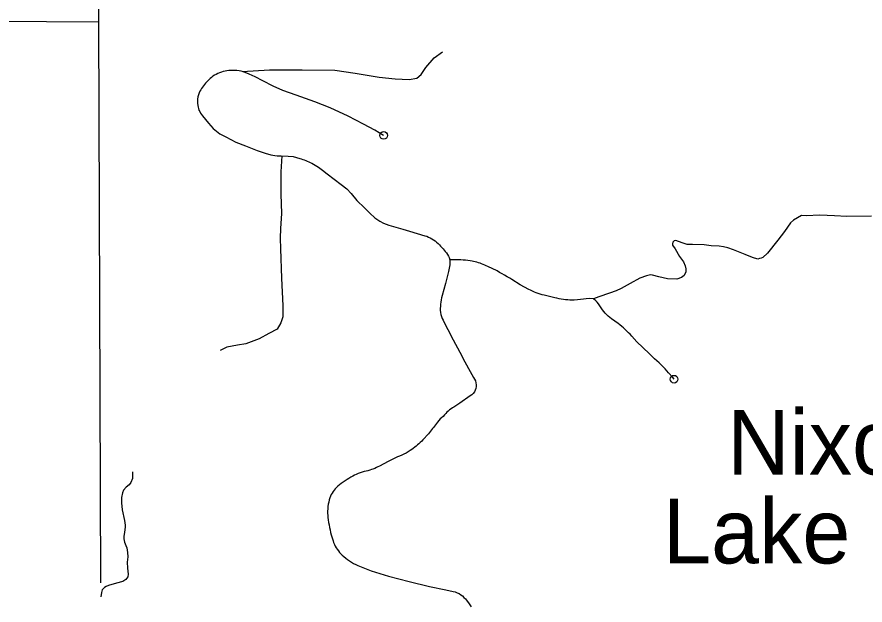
# Model space of a CAD drawing. Extents: x -19 to 366, y -4 to 359.
# Drawn here: x 139.293 to 140.343, y 191.293 to 192.02 of the extents above; entities that cross this region are included whole.
import ezdxf

# ---------------------------------------------------------------- set-up
doc = ezdxf.new("R2010")
doc.units = 0
for name, color, linetype in [('Level 2', 7, 'Continuous'), ('Level 31', 7, 'Continuous'), ('Level 32', 7, 'Continuous'), ('Level 35', 7, 'Continuous'), ('Level 60', 7, 'Continuous'), ('Level 63', 7, 'Continuous')]:
    doc.layers.add(name, color=color, linetype=linetype)

msp = doc.modelspace()

# ---------------------------------------------------------------- linework, layer by layer
at = {"layer": 'Level 2'}
for points in [[(138.4888, 192.0199), (139.3943, 192.0138)], [(139.3964, 191.3199), (139.3943, 192.0138)]]:
    msp.add_lwpolyline(points, dxfattribs=at)
at = {"layer": 'Level 31'}
for points in [[(139.7467, 191.8735), (139.7356, 191.8801), (139.7219, 191.8875), (139.7027, 191.8973), (139.6806, 191.9075), (139.6614, 191.915), (139.6385, 191.9231), (139.622, 191.929), (139.6098, 191.9344), (139.5972, 191.9411), (139.5878, 191.946), (139.5803, 191.9493), (139.573, 191.9522), (139.5704, 191.9528), (139.5678, 191.9533), (139.5651, 191.9536), (139.5625, 191.9538), (139.5599, 191.9538), (139.5572, 191.9538), (139.5551, 191.9536), (139.5527, 191.9533), (139.5504, 191.953), (139.5481, 191.9524), (139.5459, 191.9518), (139.5437, 191.951), (139.5415, 191.9501), (139.5394, 191.949), (139.5373, 191.9479), (139.5354, 191.9466), (139.5335, 191.9452), (139.5319, 191.9439), (139.5305, 191.9425), (139.529, 191.941), (139.5276, 191.9395), (139.5263, 191.938), (139.525, 191.9364), (139.5237, 191.9348), (139.5225, 191.9332), (139.5213, 191.9315), (139.5202, 191.9298), (139.5191, 191.9281), (139.5182, 191.9262), (139.5173, 191.9237), (139.5166, 191.9211), (139.5162, 191.9185), (139.5161, 191.9159), (139.5161, 191.9132), (139.5165, 191.9106), (139.5169, 191.9086), (139.5174, 191.9067), (139.5181, 191.9048), (139.519, 191.903), (139.52, 191.9012), (139.5211, 191.8994), (139.5224, 191.8978), (139.5298, 191.8885), (139.5357, 191.882), (139.5377, 191.8802), (139.5398, 191.8786), (139.5419, 191.877), (139.5441, 191.8755), (139.5464, 191.8742), (139.5488, 191.873), (139.5512, 191.8719), (139.5639, 191.8653), (139.5756, 191.8605), (139.5902, 191.8549), (139.6, 191.8516), (139.607, 191.8496), (139.6096, 191.849), (139.6121, 191.8486), (139.6147, 191.8483), (139.6173, 191.8482), (139.6199, 191.8482), (139.6284, 191.848), (139.6345, 191.8474), (139.6428, 191.8451), (139.6447, 191.8446), (139.6466, 191.8439), (139.6485, 191.8433), (139.6504, 191.8425), (139.6522, 191.8417), (139.654, 191.8409), (139.6558, 191.84), (139.6576, 191.8391), (139.666, 191.8342), (139.6709, 191.8304), (139.6769, 191.826), (139.6855, 191.8193), (139.694, 191.8128), (139.701, 191.8074), (139.7066, 191.8016), (139.7137, 191.793), (139.723, 191.7838), (139.7295, 191.7775), (139.7358, 191.7717), (139.7421, 191.7673), (139.7465, 191.7651), (139.7533, 191.7624), (139.7617, 191.7599)], [(139.6207, 191.8481), (139.6195, 191.8283), (139.6195, 191.8008), (139.6201, 191.777), (139.619, 191.7585), (139.6184, 191.7465), (139.619, 191.7334), (139.6201, 191.697), (139.6219, 191.6629), (139.6219, 191.6492), (139.6195, 191.6415), (139.6148, 191.6337), (139.6046, 191.6283), (139.5927, 191.6218), (139.576, 191.6158), (139.5659, 191.614), (139.5527, 191.6116), (139.5444, 191.6074)], [(139.7617, 191.7599), (139.7706, 191.7576), (139.7788, 191.7549), (139.7882, 191.7523), (139.7978, 191.7495), (139.8, 191.7487), (139.8022, 191.7478), (139.8044, 191.7468), (139.8065, 191.7456), (139.8085, 191.7444), (139.8104, 191.743), (139.8123, 191.7415), (139.8141, 191.7399), (139.8157, 191.7383), (139.8172, 191.7366), (139.8187, 191.735), (139.8202, 191.7333), (139.8216, 191.7316), (139.823, 191.7299), (139.8243, 191.7281), (139.8256, 191.7263), (139.8268, 191.7243), (139.8277, 191.7224), (139.8285, 191.7196)], [(139.8285, 191.7196), (139.8288, 191.7174), (139.8288, 191.7153), (139.8286, 191.7133), (139.8282, 191.7113), (139.8271, 191.705), (139.8233, 191.6905), (139.8191, 191.6755), (139.8184, 191.6728), (139.8178, 191.6701), (139.8174, 191.6674), (139.8171, 191.6646), (139.8169, 191.6619), (139.8168, 191.6598), (139.8168, 191.6572), (139.817, 191.6546), (139.8175, 191.6521), (139.8182, 191.6496), (139.8191, 191.6472), (139.8202, 191.6449), (139.8213, 191.643), (139.8263, 191.6335), (139.8327, 191.6208), (139.8409, 191.6054), (139.8472, 191.5935), (139.8537, 191.5815), (139.858, 191.574), (139.8593, 191.572), (139.8603, 191.5699), (139.861, 191.5676), (139.8613, 191.5652), (139.8613, 191.5629), (139.8608, 191.5605), (139.8601, 191.5583), (139.859, 191.5562), (139.8576, 191.5543), (139.8558, 191.5527), (139.8539, 191.5513), (139.841, 191.5422), (139.8337, 191.5375), (139.8318, 191.5365), (139.8301, 191.5353), (139.8283, 191.534), (139.8267, 191.5326), (139.8251, 191.5311), (139.8236, 191.5295), (139.822, 191.5278), (139.8202, 191.526), (139.8184, 191.5243), (139.8166, 191.5228), (139.8133, 191.5187), (139.8121, 191.5171), (139.8109, 191.5155), (139.8097, 191.5139), (139.8085, 191.5123), (139.8072, 191.5108), (139.806, 191.5092), (139.8047, 191.5077), (139.8035, 191.5061), (139.8022, 191.5046), (139.7954, 191.497), (139.7938, 191.4954), (139.7921, 191.4938), (139.7904, 191.4922), (139.7887, 191.4907), (139.787, 191.4892), (139.7852, 191.4878), (139.7834, 191.4864), (139.7816, 191.4851), (139.7795, 191.4836), (139.7769, 191.482), (139.7744, 191.4806), (139.7717, 191.4792), (139.7691, 191.478), (139.7664, 191.4769), (139.7637, 191.4759), (139.7524, 191.4701), (139.7417, 191.4644), (139.7397, 191.4635), (139.7377, 191.4626), (139.7356, 191.4617), (139.7335, 191.4609), (139.7315, 191.4601), (139.7294, 191.4594), (139.7272, 191.4588), (139.7251, 191.4582), (139.7226, 191.4577), (139.7201, 191.457), (139.7176, 191.4562), (139.7152, 191.4553), (139.7128, 191.4543), (139.7105, 191.4531), (139.7087, 191.4522), (139.7062, 191.4508), (139.7038, 191.4493), (139.7014, 191.4478), (139.699, 191.4462), (139.6966, 191.4446), (139.6943, 191.443), (139.692, 191.4413)], [(140.0066, 191.6715), (140.0012, 191.6717), (139.9975, 191.6713), (139.9939, 191.6708), (139.9902, 191.6704), (139.9865, 191.67), (139.9827, 191.6696), (139.98, 191.6697), (139.9773, 191.6699), (139.9746, 191.6701), (139.9719, 191.6703), (139.9692, 191.6707), (139.9665, 191.671), (139.9638, 191.6715), (139.9611, 191.672), (139.9585, 191.6726), (139.9454, 191.6759), (139.9429, 191.6765), (139.9405, 191.6773), (139.9381, 191.6781), (139.9357, 191.6789), (139.9334, 191.6798), (139.931, 191.6808), (139.9283, 191.682), (139.9264, 191.6828), (139.9157, 191.6887), (139.9054, 191.6951), (139.9027, 191.6968), (139.8996, 191.6987), (139.8965, 191.7005), (139.8934, 191.7023), (139.8902, 191.7041), (139.8871, 191.7059), (139.8756, 191.7114), (139.8738, 191.7123), (139.8719, 191.7131), (139.87, 191.7139), (139.868, 191.7147), (139.8661, 191.7154), (139.8641, 191.7161), (139.8621, 191.7167), (139.8601, 191.7172), (139.8581, 191.7177), (139.8561, 191.7181), (139.8539, 191.7185), (139.851, 191.7189), (139.8481, 191.7192), (139.8452, 191.7194), (139.8423, 191.7195), (139.8393, 191.7195), (139.8355, 191.7196), (139.8321, 191.7196), (139.8285, 191.7196)], [(140.1063, 191.572), (140.1048, 191.5742), (140.0995, 191.5798), (140.095, 191.5849), (140.0878, 191.5924), (140.0821, 191.5973), (140.0758, 191.6033), (140.0676, 191.6112), (140.0603, 191.6183), (140.0538, 191.6254), (140.0518, 191.6275), (140.0498, 191.6295), (140.0478, 191.6315), (140.0457, 191.6335), (140.0436, 191.6354), (140.0414, 191.6373), (140.0392, 191.6391), (140.037, 191.6409), (140.0289, 191.6467), (140.0268, 191.6483), (140.0247, 191.6499), (140.0228, 191.6517), (140.0209, 191.6536), (140.0192, 191.6555), (140.0175, 191.6576), (140.0126, 191.6653), (140.011, 191.6671), (140.0092, 191.6687), (140.0066, 191.6715)], [(139.692, 191.4413), (139.6898, 191.4395), (139.6882, 191.4381), (139.6867, 191.4365), (139.6854, 191.4348), (139.6841, 191.433), (139.6829, 191.4311), (139.6819, 191.4292), (139.681, 191.4272), (139.6802, 191.4252), (139.6794, 191.4226), (139.6787, 191.4199), (139.6782, 191.4172), (139.6777, 191.4145), (139.6774, 191.4117), (139.6773, 191.4089), (139.6773, 191.4061), (139.6774, 191.4033), (139.6777, 191.401), (139.6781, 191.3979), (139.6786, 191.3948), (139.6791, 191.3917), (139.6797, 191.3886), (139.6804, 191.3855), (139.6811, 191.3825), (139.6819, 191.3794), (139.6833, 191.3744), (139.684, 191.3721), (139.6848, 191.3699), (139.6857, 191.3677), (139.6868, 191.3656), (139.6879, 191.3635), (139.6892, 191.3616), (139.6906, 191.3596), (139.6921, 191.3578), (139.6938, 191.3561), (139.6955, 191.3544), (139.6975, 191.3527), (139.6997, 191.3508), (139.702, 191.349), (139.7044, 191.3473), (139.7069, 191.3457), (139.7095, 191.3442), (139.7121, 191.3429), (139.7147, 191.3416), (139.7313, 191.3349), (139.7528, 191.3285), (139.7783, 191.3217), (139.8035, 191.3155), (139.8238, 191.3115), (139.8328, 191.3095), (139.8353, 191.3088), (139.8377, 191.3079), (139.84, 191.3068), (139.8422, 191.3054), (139.8442, 191.3039), (139.8461, 191.3021), (139.8479, 191.3002), (139.8492, 191.2985), (139.8525, 191.294), (139.8551, 191.2905)]]:
    msp.add_lwpolyline(points, dxfattribs=at)
for centre in [(139.7467, 191.8735), (140.1063, 191.572)]:
    msp.add_circle(centre, 0.00473, dxfattribs=at)
at = {"layer": 'Level 32'}
for points in [[(139.5716, 191.9525), (139.6052, 191.9547), (139.6458, 191.9547), (139.6864, 191.9541), (139.7114, 191.9505), (139.7413, 191.9457), (139.7609, 191.9433), (139.7782, 191.9427), (139.7878, 191.9445), (139.7932, 191.9487), (139.7991, 191.9576), (139.8093, 191.9696), (139.8194, 191.9767)], [(140.3507, 191.7736), (140.32, 191.7732), (140.3047, 191.7742), (140.2867, 191.7747), (140.2698, 191.7742), (140.2639, 191.7745), (140.2588, 191.7716), (140.2542, 191.7688), (140.2503, 191.7655), (140.243, 191.7546), (140.2345, 191.7438), (140.2219, 191.7279), (140.2159, 191.7225), (140.2139, 191.7217), (140.2119, 191.7211), (140.2098, 191.7206), (140.2034, 191.7224), (140.1944, 191.7261), (140.1796, 191.732), (140.1729, 191.7345), (140.1672, 191.7358), (140.162, 191.7364), (140.1523, 191.7371), (140.1435, 191.7381), (140.1289, 191.7384), (140.1225, 191.7387), (140.1163, 191.7407), (140.1082, 191.7435), (140.1062, 191.743), (140.1048, 191.7416), (140.1041, 191.7396), (140.1043, 191.7376), (140.1074, 191.7333), (140.1131, 191.7238), (140.1177, 191.7171), (140.1199, 191.7122), (140.1209, 191.7085), (140.1206, 191.7049), (140.1187, 191.7002), (140.1156, 191.6976), (140.1098, 191.6959), (140.0979, 191.6961), (140.0875, 191.6985), (140.0796, 191.7007), (140.0771, 191.7011), (140.0722, 191.7), (140.0639, 191.6968), (140.0518, 191.6905), (140.0409, 191.6843), (140.0344, 191.6814), (140.0261, 191.6784), (140.0129, 191.6738), (140.0066, 191.6715)], [(139.4357, 191.4576), (139.4358, 191.4528), (139.4357, 191.4492), (139.4337, 191.4444), (139.4317, 191.4413), (139.4279, 191.4384), (139.4246, 191.4348), (139.4234, 191.4315), (139.4221, 191.4257), (139.4221, 191.419), (139.4232, 191.4106), (139.4259, 191.397), (139.4267, 191.3916), (139.4268, 191.389), (139.4257, 191.3826), (139.425, 191.3774), (139.4251, 191.3746), (139.4261, 191.3705), (139.4275, 191.3663), (139.4289, 191.3633), (139.4297, 191.3575), (139.4301, 191.3521), (139.4294, 191.3458), (139.4296, 191.3381), (139.4303, 191.3308), (139.4299, 191.3276), (139.4277, 191.3243), (139.4237, 191.3216), (139.4158, 191.3196), (139.4062, 191.317), (139.403, 191.3156), (139.4011, 191.3142), (139.3984, 191.3116), (139.3975, 191.3083), (139.3964, 191.3028)]]:
    msp.add_lwpolyline(points, dxfattribs=at)
at = {"layer": 'Level 60'}
for points in [[(146.7783, 1.697), (146.5788, 10.3131), (146.3785, 18.9294), (146.1776, 27.5458), (145.9759, 36.1624), (145.7736, 44.7791), (145.5705, 53.396), (145.3668, 62.013), (145.1624, 70.6301), (144.9572, 79.2474), (144.7514, 87.8648), (144.5449, 96.4823), (144.3377, 105.1), (144.1299, 113.7179), (143.9213, 122.3359), (143.712, 130.954), (143.5021, 139.5723), (143.2915, 148.1907), (143.0802, 156.8092), (142.8682, 165.4279), (142.6555, 174.0468), (142.4422, 182.6658), (142.2282, 191.2849), (142.0135, 199.9042), (141.7981, 208.5236), (141.582, 217.1432), (141.3653, 225.7629), (141.1479, 234.3828), (140.9298, 243.0028), (140.711, 251.623), (140.4916, 260.2433), (140.2715, 268.8638), (140.0508, 277.4844), (139.8293, 286.1051), (139.6072, 294.726), (139.3845, 303.3471), (139.161, 311.9683), (138.937, 320.5896), (138.7122, 329.2111), (138.4868, 337.8328), (138.2607, 346.4546)], [(139.4406, 1.5315), (139.2511, 10.1473), (139.0608, 18.7633), (138.8699, 27.3793), (138.6784, 35.9956), (138.4861, 44.6119), (138.2932, 53.2285), (138.0997, 61.8451), (137.9055, 70.4619), (137.7106, 79.0789), (137.5151, 87.6959), (137.319, 96.3132), (137.1221, 104.9306), (136.9247, 113.5481), (136.7265, 122.1658), (136.5278, 130.7836), (136.3283, 139.4016), (136.1282, 148.0197), (135.9275, 156.6379), (135.7261, 165.2564), (135.5241, 173.8749), (135.3214, 182.4936), (135.1181, 191.1125), (134.9141, 199.7315), (134.7095, 208.3506), (134.5043, 216.9699), (134.2984, 225.5894), (134.0919, 234.209), (133.8847, 242.8288), (133.6769, 251.4487), (133.4685, 260.0687), (133.2594, 268.6889), (133.0497, 277.3093), (132.8393, 285.9298), (132.6283, 294.5504), (132.4167, 303.1713), (132.2044, 311.7922), (131.9916, 320.4133), (131.778, 329.0346), (131.5639, 337.656), (131.3491, 346.2776)], [(0, 189.5162), (7.1121, 189.5206), (14.2243, 189.5339), (21.3364, 189.556), (28.4484, 189.5869), (35.5605, 189.6267), (42.6725, 189.6754), (49.7844, 189.7329), (56.8962, 189.7992), (64.0079, 189.8744), (71.1196, 189.9584), (78.2311, 190.0512), (85.3425, 190.1529), (92.4538, 190.2635), (99.5649, 190.3829), (106.6759, 190.5111), (113.7867, 190.6482), (120.8974, 190.7941), (128.0078, 190.9489), (135.1181, 191.1125), (142.2282, 191.2849), (149.338, 191.4662), (156.4476, 191.6563), (163.5569, 191.8553), (170.666, 192.0631), (177.7749, 192.2798), (184.8835, 192.5053), (191.9917, 192.7396), (199.0997, 192.9828), (206.2074, 193.2348), (213.3147, 193.4956), (220.4218, 193.7653), (227.5285, 194.0438), (234.6348, 194.3312), (241.7408, 194.6274), (248.8464, 194.9324), (255.9516, 195.2463), (263.0564, 195.569), (270.1608, 195.9005), (277.2648, 196.2409), (284.3683, 196.5901), (291.4715, 196.9481), (298.5741, 197.315), (305.6763, 197.6907), (312.7781, 198.0753), (319.8793, 198.4686), (326.9801, 198.8708), (334.0804, 199.2818), (341.1801, 199.7017)]]:
    msp.add_spline(points, degree=3, dxfattribs=at)
at = {"layer": 'Level 63'}
msp.add_lwpolyline([(139.3943, 192.0138), (139.3968, 192.5251)], dxfattribs=at)

# ---------------------------------------------------------------- texts
at = {"layer": 'Level 35'}
for s, p in [('Nixon', (140.172, 191.454)), ('Lake', (140.0925, 191.3441))]:
    msp.add_text(s, height=0.08, dxfattribs=at).set_placement(p)

doc.saveas('drawing.dxf')
